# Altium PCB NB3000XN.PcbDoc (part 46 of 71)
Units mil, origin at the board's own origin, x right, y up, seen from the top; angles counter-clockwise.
Board outline 9527.56 x 6929.77 mil, 6 copper layers (Top Layer, GND+SHIELD, MidLayer1, MidLayer2, P2 - 3V3+5V0, Bottom Layer), stack 62.375 mil thick; 832 components, 1027 nets, 4655 pads, 4981 vias.
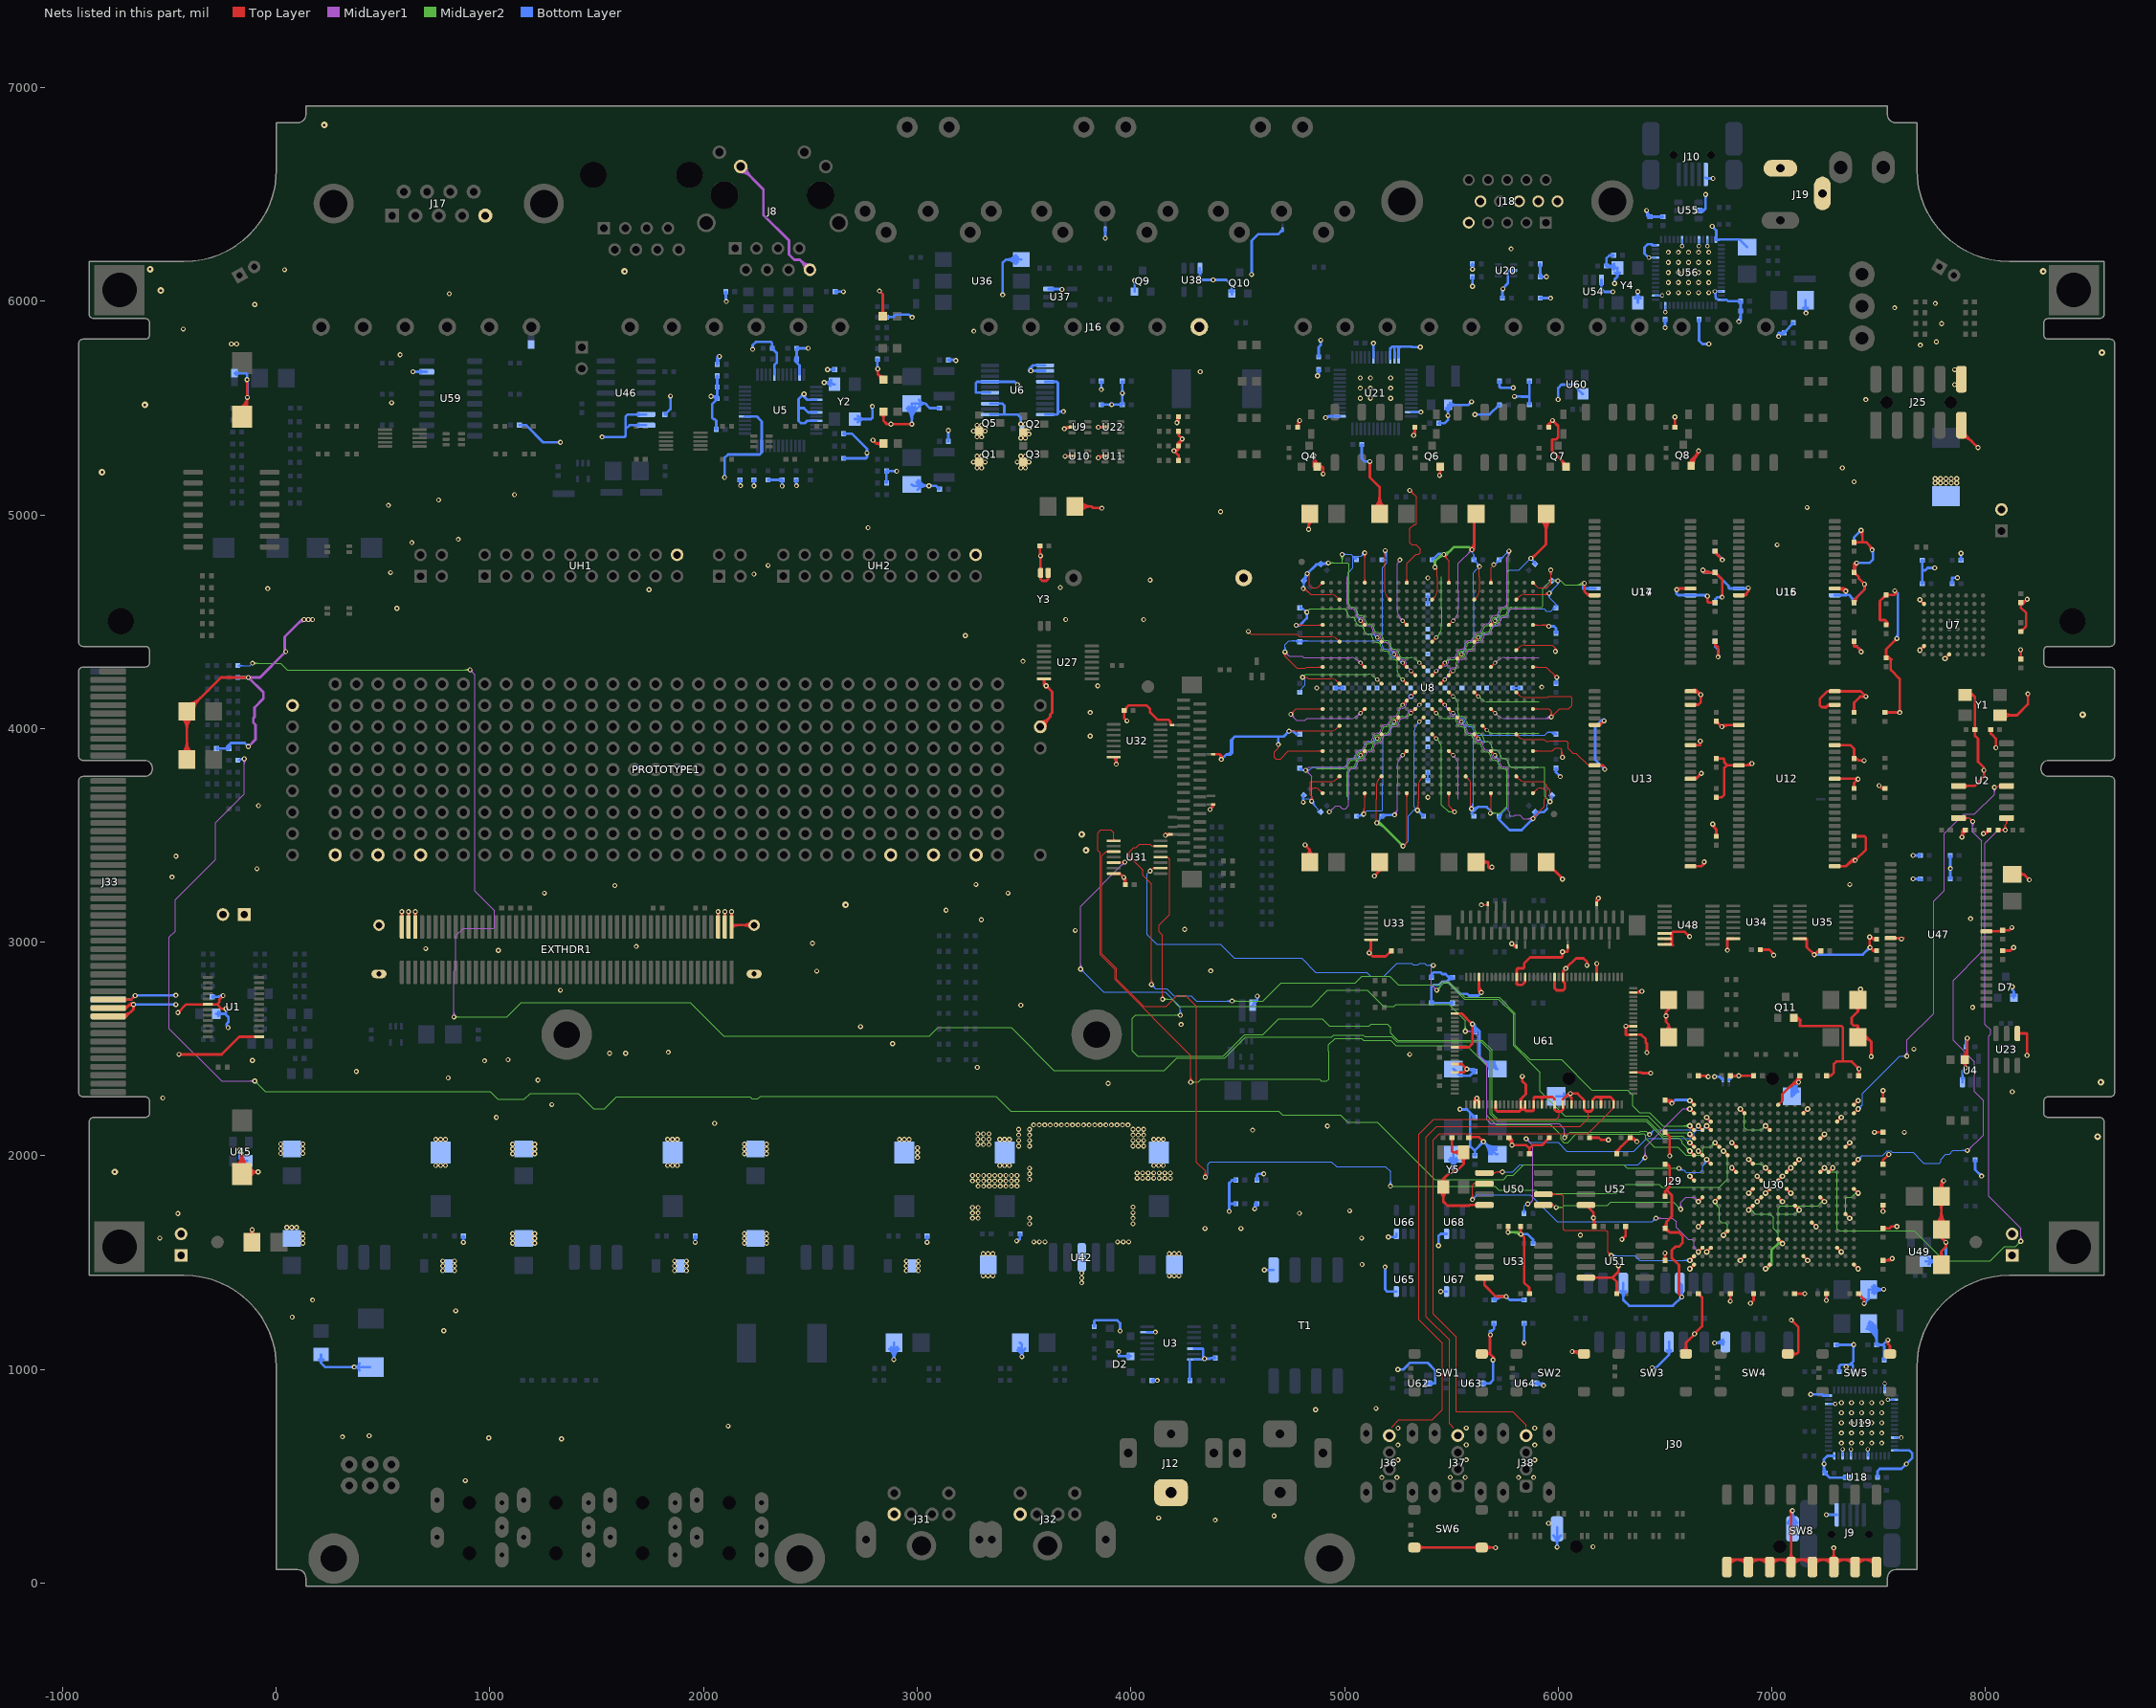
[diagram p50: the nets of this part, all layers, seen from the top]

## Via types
v1: diameter 23, hole 11.81, Top Layer to Bottom Layer, 3672 vias
v2: diameter 26, hole 11.81, Top Layer to Bottom Layer, 461 vias
v3: diameter 19, hole 11.81, Top Layer to Bottom Layer, tented both sides, 396 vias
v4: diameter 23.62, hole 11.81, Top Layer to Bottom Layer, 288 vias
v5: diameter 20, hole 11.81, Top Layer to Bottom Layer, 91 vias
v6: diameter 23, hole 11.81, Top Layer to Bottom Layer, tented both sides, 50 vias
v7: diameter 31, hole 11.81, Top Layer to Bottom Layer, 15 vias
v8: diameter 27.56, hole 11.81, Top Layer to Bottom Layer, tented both sides, 4 vias
v9: diameter 29, hole 11.81, Top Layer to Bottom Layer, 3 vias
v10: diameter 21, hole 11.81, Top Layer to Bottom Layer, 1 vias

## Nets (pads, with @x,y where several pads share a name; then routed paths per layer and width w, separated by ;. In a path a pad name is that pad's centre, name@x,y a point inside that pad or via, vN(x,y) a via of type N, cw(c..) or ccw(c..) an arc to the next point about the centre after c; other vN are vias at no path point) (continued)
GND: (continued)
  Bottom Layer w12: v1@7431.86,1313.87 ccw(c7431.86,1327.15) 7441.25,1317.76 ccw(c7450.64,1308.37) v1@7437.36,1308.37 ; v1(7433.86,4676.04) 7433.86,4651.04 7385.19,4602.37 ; v1@7453.69,2975.04 cw(c7440.41,2975.04) 7449.8,2965.65 cw(c7459.19,2956.26) v1@7459.19,2969.54 ; v1@7465.64,4832.71 cw(c7446.59,4813.66) 7473.52,4813.66 ; C93.2@7469.71,1360.69 cw(c7497.3,1338.74) 7497.3,1374 cw(c7497.3,1409.26) C93.2@7469.71,1387.31 ; C93.2@7479.1,1353.22 cw(c7522.19,1318.94) v1@7522.19,1374 ; C93.2@7479.11,1394.78 ccw(c7522.19,1429.05) v1@7522.19,1374 ; v4(7480,2110) v4@7481.86,2110 ; C90.1@7494.33,495 7494.33,524.33 7505,535 7606.86,535 v1(7629.73,557.88) 7656.86,585 7656.86,608.37 ; 7506.93,1374 ccw(c7506.93,1391.97) v1@7519.64,1379.26 ; v1@7522.52,1374.33 v1@7522.19,1374 ; v1@7522.52,1374.37 v1(7523.52,1375.37) ; v4(7547.7,2006.4) v4@7548.6,2006.4 ; v1(7575.52,4645.04) 7590.19,4630.37 7590.19,4426.37 v1(7585.19,4421.37) ; v1@7581.3,4425.26 ccw(c7559.84,4446.72) 7590.19,4446.72 ; v1@7660,3405 v1(7661.18,3406.18) C238.2@7695.39,3406.18 C238.2@7694.21,3405 ; v1@7661.18,3296.18 C222.2@7695.39,3296.18 ; v1@7665.07,3292.48 cw(c7673.99,3283.56) 7673.99,3296.18 ; v1@7665.07,3300.26 ccw(c7674.92,3310.12) 7674.92,3296.18 ; v1@7665.07,3402.29 cw(c7674.46,3392.9) 7674.46,3406.18 cw(c7674.46,3419.46) v1@7665.07,3410.07 ; C222.2@7691.28,3292.07 ccw(c7681.36,3282.15) 7681.36,3296.18 ccw(c7681.36,3310.21) C222.2@7691.28,3300.29 ; C238.2@7691.28,3402.07 ccw(c7681.36,3392.15) 7681.36,3406.18 ccw(c7681.36,3420.21) C238.2@7691.28,3410.29 ; C222.2@7695.39,3291.71 C222.2@7699.52,3291.71 ; C228.2@7699.55,4682.11 ccw(c7689.63,4692.03) 7703.66,4692.03 ccw(c7717.69,4692.03) C228.2@7707.77,4682.11 ; C227.2@7699.55,4783.89 cw(c7689.63,4773.97) 7703.66,4773.97 cw(c7717.69,4773.97) C227.2@7707.77,4783.89 ; C228.2@7703.66,4678 7703.66,4740 ; C227.2@7703.66,4788 7703.66,4740 ; U49.1@7719.07,1506.69 7806.69,1506.69 7815.19,1515.19 v1(7815.19,1595.04) ; U49.1@7733.62,1492.14 cw(c7768.75,1457.02) 7768.75,1506.69 cw(c7768.75,1556.36) U49.1@7733.62,1521.24 ; v1@7758.3,4748.15 ccw(c7748.91,4738.76) 7748.91,4752.04 ccw(c7748.91,4765.32) v1@7758.3,4755.93 ; v1(7762.19,4752.04) 7728.86,4752.04 7717.86,4741.04 7704.7,4741.04 7703.66,4740 ; C254.2@7831.28,3300.29 ccw(c7821.36,3310.21) 7835.39,3310.21 ccw(c7849.42,3310.21) C254.2@7839.5,3300.29 ; C253.2@7831.28,3402.07 cw(c7821.36,3392.15) 7835.39,3392.15 cw(c7849.42,3392.15) C253.2@7839.5,3402.07 ; v1@7831.64,3341.15 cw(c7822.58,3332.1) 7835.39,3332.1 ; v1@7831.64,3348.93 ccw(c7822.58,3357.99) 7835.39,3357.99 ; C254.2@7835.39,3296.18 7835.39,3344.9 v1(7835.52,3345.04) 7835.39,3345.18 C253.2@7835.39,3406.18 ; 7835.39,3331.43 cw(c7849.14,3331.43) v1@7839.41,3341.15 ; 7835.39,3358.65 ccw(c7849.14,3358.65) v1@7839.41,3348.93 ; C248.2@7839.55,4682.11 ccw(c7829.63,4692.03) 7843.66,4692.03 ccw(c7857.69,4692.03) C248.2@7847.77,4682.11 ; C248.2@7843.66,4678 7843.66,4705.9 7843.8,4706.04 v1(7868.52,4706.04) ; v1@7864.64,4702.15 ccw(c7855.25,4692.76) 7855.25,4706.04 ccw(c7855.25,4719.32) v1@7864.64,4709.93 ; C247.2@7880.89,4792.11 ccw(c7870.97,4802.03) 7885,4802.03 ccw(c7899.03,4802.03) C247.2@7889.11,4792.11 ; v1@7881.3,4816.49 cw(c7872.37,4807.56) 7885,4807.56 ; v1@7881.86,4823.71 v1@7885,4820.56 ; C247.2@7885,4788 7885,4820.37 v1@7885,4820.56 ; 7885,4806.64 cw(c7898.93,4806.64) v1@7889.08,4816.49 ; v1(7885.19,4820.37) v1@7885,4820.56 ; U4.3@7888.49,2362.77 ccw(c7878.57,2372.69) 7892.6,2372.69 ccw(c7906.63,2372.69) U4.3@7896.71,2362.77 ; U4.3@7892.6,2344.88 7892.6,2397.78 v1(7906.86,2412.04) ; C39.1@7905.22,2514.11 ccw(c7895.3,2524.03) 7909.33,2524.03 ccw(c7923.36,2524.03) C39.1@7913.44,2514.11 ; C39.1@7909.33,2510 7909.33,2545.37 7914.66,2550.71 v1(7914.86,2550.71) ; 7909.33,2524.09 cw(c7941.48,2524.09) v1@7918.75,2546.82 ; R163.1@7947.42,1977.41 cw(c7938.34,1968.33) 7951.18,1968.33 cw(c7964.02,1968.33) R163.1@7954.94,1977.41 ; R163.1@7951.18,1981.67 7951.18,1935.68 7981.76,1905.1 v1@7981.86,1905 ; 7972.14,1914.72 ccw(c7981.86,1924.44) v1@7981.86,1910.69 ; 7972.61,1914.25 cw(c7963.55,1905.19) v1@7976.36,1905.19 ; D7.1@8124.12,2749.06 ccw(c8104.11,2769.06) 8132.4,2769.06 ccw(c8160.69,2769.06) D7.1@8140.69,2749.06 ; v1@8126.9,2793.42 8124.74,2795.59 8124.65,2795.59 8125.19,2795.04 v1(8125.19,2791.71) 8125.19,2777.21 8132.4,2770 D7.1@8132.4,2739.79 ; -239.81,2665 -223.5,2648.69 -223.5,2626.09 -233,2616.59 ; 210,1030 228.29,1011.71 v1(365.19,1011.71) v1@365.19,1011.81 ; v1@2435,5141.71 2435.19,5141.71 v1(2435.19,5136.71) 2432.52,5139.37 2434.86,5141.71 v1@2435,5141.71 ; v1@2435,5141.71 2434,5142.71 R41.2@2434,5163.82 2435,5163.82 v1@2435,5141.71 ; 2435.67,5715.97 cw(c2449.7,5715.97) 2439.78,5725.89 ccw(c2449.7,5715.97) 2435.67,5715.97 ; 2435.67,5715.97 ccw(c2421.64,5715.97) 2431.56,5725.89 cw(c2421.64,5715.97) 2435.67,5715.97 ; C47.1@2435.67,5775.04 2438.15,5777.52 C47.1@2440.63,5780 ; C47.1@2435.67,5775.04 C47.1@2435.67,5780 C47.1@2440.63,5780 ; 2445,5455 2445,5500 ; U38.3@4319.14,6137.23 cw(c4308.54,6126.63) 4323.52,6126.63 ccw(c4308.54,6126.63) U38.3@4319.14,6137.23 ; U38.3@4319.14,6137.23 cw(c4309.21,6127.31) 4323.24,6127.31 cw(c4337.27,6127.31) U38.3@4327.35,6137.23 ; U38.3@4327.35,6137.23 ccw(c4336.6,6127.99) 4323.52,6127.99 cw(c4336.6,6127.99) U38.3@4327.35,6137.23 ; 4455,3879.04 4466.19,3879.04 4474.86,3887.71 4474.86,3951.04 ; 4455,3879.04 4468.86,3892.9 4468.86,3945.04 4474.86,3951.04 ; 4474.86,3951.04 4485.86,3962.04 4690.19,3962.04 ; v1@4917.69,4774.2 v1(4924.52,4775.04) 4918.52,4775.04 v1@4917.69,4774.2 ; 5235,5788.21 5263.21,5788.21 ; 5415.06,2858.37 5449.91,2858.37 5457.78,2850.5 5473.06,2850.5 5493.52,2830.04 ; 5480.19,2816.71 5493.52,2830.04 ; 5573.96,2216.71 5587.52,2203.14 ; 5573.96,2216.71 5587.52,2203.14 ; 5587.52,2203.14 C338.2@5610,2180.67 5587.52,2203.14 ; 5587.52,2203.14 5587.52,2041.71 5592.19,2041.71 5608.86,2025.04 ; 5594.19,3603.37 5604.86,3614.04 ; 5594.19,3603.37 5604.86,3614.04 ; C338.2@5600.08,2190.59 cw(c5590.16,2180.67) 5604.19,2180.67 ccw(c5590.16,2180.67) C338.2@5600.08,2190.59 ; C338.2@5600.08,2190.59 ccw(c5610,2200.51) 5610,2186.48 cw(c5610,2200.51) C338.2@5600.08,2190.59 ; 5604.86,3614.04 5606.86,3616.04 ; 5604.86,3614.04 5606.86,3616.04 ; 5606.86,3616.04 5624.19,3633.37 ; v1@5739.52,6058.37 5740.36,6059.21 5764.52,6083.37 5764.52,6135.41 5770.82,6141.71 ; v1@6006.9,3775 v1(6010,3775) v1@6006.86,3778.14 ; v1@6006.86,3775.04 v1@6006.9,3775 ; v1@6006.86,3775.04 v1@6006.86,3778.14 ; 6122.52,4667.43 cw(c6135.8,4667.43) 6126.41,4676.82 ccw(c6135.8,4667.43) 6122.52,4667.43 ; 6122.52,4667.43 ccw(c6109.25,4667.43) 6118.64,4676.82 cw(c6109.25,4667.43) 6122.52,4667.43 ; 6130,4655.75 6115.9,4655.75 6115.9,4674.08 v1(6122.52,4680.71) 6122.52,4663.22 6130,4655.75 ; 6681.86,6425 6690.19,6433.33 ; 7348.52,4625.04 7362.52,4625.04 7385.19,4602.37 ; 5765.93,6136.82 cw(c5780.25,6122.5) 5783.05,6142.55 ccw(c5780.25,6122.5) 5765.93,6136.82 ; C324.2@5895.78,3613.7 ccw(c5908.63,3626.55) 5908.63,3608.37 cw(c5908.63,3626.55) C324.2@5895.78,3613.7
  other v1: 6163,170 5955,280 4395,295 4130,305 4670,315 885,480 5174.79,494.61 5245,494.61 5814.79,494.61 5885,494.61 5494.79,495 5565,495 5250.17,576.71 5890.17,576.71 5570.17,577.1 5250.17,646.92 5570.17,647.31 5890.17,646.92 1335,675 995,680 310,685 435,690 5250.17,725.66 5890.17,725.66 5570.17,726.05 2115,735 5147,818 7348,1013 7383.52,1116.71 4115,1175 784.17,1181.5 75,1245 840,1275 170,1325 5450,1364.88 3770,1406.01 3770,1428.51 3309.02,1438.07 3331.52,1438.07 3354.02,1438.07 4180,1438.07 4202.5,1438.07 4225,1438.07 3770,1451.01 779.17,1462.5 835,1462.5 1864.17,1462.5 1920,1462.5 2949.17,1462.5 3005,1462.5 779.17,1485 835,1485 1864.17,1485 1920,1485 2949.17,1485 3005,1485 5082.52,1491.71 779.17,1507.5 835,1507.5 1864.17,1507.5 1920,1507.5 2949.17,1507.5 3005,1507.5 3309.02,1541.93 3331.52,1541.93 3354.02,1541.93 4180,1541.93 4202.5,1541.93 4225,1541.93 125,1590.98 1106.14,1590.98 1210,1590.98 2191.14,1590.98 2295,1590.98 3546,1597.5 3572,1597.5 3597.99,1597.5 3938.01,1597.5 3964,1597.5 3990,1597.5 125,1613.48 1106.14,1613.48 1210,1613.48 2191.14,1613.48 2295,1613.48 -545,1615 5080,1615 6104,1629 125,1635.98 1106.14,1635.98 1210,1635.98 2191.14,1635.98 2295,1635.98 4347,1660 4515,1660 50.08,1664.92 72.58,1664.92 95.08,1664.92 3526,1682.01 4010,1682.01 3259.02,1708 3285.02,1708 3526,1708.01 4010,1708.01 -460,1730 4789,1731 3259.02,1733 3285.02,1733 4010,1734 5024,1743 3259.02,1758 3285.02,1758 4010,1760 3285.02,1858 3311.01,1858 3337.01,1858 3363,1858 3389,1858 3415,1858 3440.99,1858 3466.99,1858 3259.02,1883 3285.02,1883 3311.01,1883 3337.01,1883 3363,1883 3389,1883 3415,1883 3440.99,1883 3466.99,1883 3526,1889.98 4029.02,1895 4055.02,1895 4081.01,1895 4107.01,1895 4133,1895 4159,1895 4185,1895 7981.86,1905.19 3259.02,1908 3285.02,1908 3311.01,1908 3337.01,1908 3363,1908 3389,1908 3415,1908 3440.99,1908 3466.99,1908 3526,1915.98 4029.02,1920 4055.02,1920 4081.01,1920 4107.01,1920 4133,1920 4159,1920 4185,1920 3526.01,1941.97 747.01,1954.88 769.51,1954.88 792.01,1954.88 1832.01,1954.88 1854.51,1954.88 1877.01,1954.88 3386.46,1954.88 3408.96,1954.88 3431.46,1954.88 4107.01,1954.88 4129.51,1954.88 4152.01,1954.88 3001.3,1992.64 1106.14,2010 1210,2010 2191.14,2010 2295,2010 21.14,2010.98 125,2010.98 3001.3,2015.14 1106.14,2032.5 1210,2032.5 2191.14,2032.5 2295,2032.5 21.14,2033.48 125,2033.48 3001.3,2037.64 3474.99,2045.96 3526.01,2045.96 4009.99,2045.96 4034.99,2045.96 4059.99,2045.96 3284.02,2053 3310.02,2053 3336.01,2053 1106.14,2055 1210,2055 2191.14,2055 2295,2055 21.14,2055.98 125,2055.98 3474.99,2071.95 3526.01,2071.95 4009.99,2071.95 4034.99,2071.95 4059.99,2071.95 747.01,2076.93 769.51,2076.93 792.01,2076.93 1832.01,2076.93 1854.51,2076.93 1877.01,2076.93 2917.01,2076.93 2939.51,2076.93 2962.01,2076.93 3386.46,2076.93 3408.96,2076.93 3431.46,2076.93 4107.01,2076.93 4129.51,2076.93 4152.01,2076.93 3284.02,2078 3310.02,2078 3336.01,2078 3474.99,2097.95 3526.01,2097.95 4009.99,2097.95 4034.99,2097.95 4059.99,2097.95 3284.02,2103 3310.02,2103 3336.01,2103 7620,2110 4570,2120 3474.99,2123.94 3526.01,2123.94 4009.99,2123.94 4034.99,2123.94 4059.99,2123.94 4920,2140 3545,2145 3571,2145 3596.99,2145 3622.99,2145 3648.98,2145 3674.98,2145 3700.98,2145 3726.97,2145.01 3752.97,2145.01 3778.96,2145.01 3804.96,2145.01 3830.96,2145.01 3856.95,2145.01 3882.95,2145.01 3908.94,2145.01 3934.94,2145.01 3960.94,2145.01 3986.93,2145.01 2052,2152 1030,2180 1290,2240 -531,2271 8125,2300 3893.94,2338.94 1225,2355 805,2365 6702.52,2370.71 375,2395 3281,2414 975,2445 1085,2450 5305,2475 1560,2480 1635,2480 1835,2485 7665,2500 2885,2525 2735,2605 4235,2615 7940,2695 1330,2775 7415,2780 2530,2865 4374,2866 7009,2939 700,2970 1685,2980 5782.86,2993.04 2510,2995 3740,3055 4252,3060 3300,3105 7930,3110 619.35,3143.04 650.85,3143.04 2068.17,3143.04 2099.67,3143.04 2131.17,3143.04 3135,3150 1255,3230 3425,3230 1585,3265 3275,3270 7365,3270 7661.18,3296.37 -90,3344 -83,3639 5390,3678 3810,3965 3810,4075 4870,4190 5923,4194 3845,4200 3495,4315 45,4360 3225,4435 3695,4510 4060,4510 565,4563 1745,4650 -40,4655 3670,4660 4090,4695 5390,4705 2236,4723 535,4730 2302,4764 7025,4860 635,4870 852,4886 2770,4940 4420,5015 7165,5035 525,5045 760,5070 1115,5095 7385,5155 3280,5220 3301.57,5220 3485,5220 3506.57,5220 7330,5220 3263.19,5247.6 3318.39,5247.6 3468.19,5247.6 3523.39,5247.6 3280,5275.2 3301.57,5275.2 3485,5275.2 3506.57,5275.2 3485,5360 3506.57,5360 3280,5365 3301.57,5365 3523.39,5378.6 3263.19,5392.6 3318.39,5392.6 3689,5403 3523.39,5406.6 3280,5420.2 3301.57,5420.2 2877,5425 3506.57,5425.2 5484.37,5465 3685,5483.57 3910,5516.37 540,5525 7440,5540 3861.86,5586.9 7855,5610 4325,5670 7855,5680 580,5750 2490,5780 7695,5795 5135.19,5804.04 7770,5810 3265,5860 -435,5870 7795,5895 7160,5945 7575,5970 -100,5985 7765,5990 810,6035 6372.5,6045.19 4385,6100.04 39.01,6147.63 5780,6245 3880,6295 6690,6500
  other v4: 4865,812 -112,2446 3485,2705 1040,2962 -488,3305 -469,3403 7764.51,5149.9 7789.61,5149.9 7814.7,5149.9 7839.8,5149.9 7864.8,5150 7764.51,5169.9 7789.61,5169.9 7814.7,5169.9 7839.8,5169.9 7864.8,5170 5074.13,5546.38 5121.38,5546.38 5215.87,5546.38 5074.13,5593.62 5121.38,5593.62 5215.87,5593.62 5074.13,5640.87 5121.38,5640.87 5215.87,5640.87 -210,5800 -185,5800
  other v5: 7528.27,935.66
  other v6: 7325.51,655.51 7372.76,655.51 7420,655.51 7467.24,655.51 7514.49,655.51 7325.51,702.76 7372.76,702.76 7420,702.76 7467.24,702.76 7514.49,702.76 7325.51,750 7372.76,750 7420,750 7467.24,750 7514.49,750 7325.51,797.24 7372.76,797.24 7420,797.24 7467.24,797.24 7514.49,797.24 7325.51,844.49 7372.76,844.49 7420,844.49 7467.24,844.49 7514.49,844.49 6515.51,6040.51 6562.76,6040.51 6610,6040.51 6657.24,6040.51 6704.49,6040.51 6515.51,6087.76 6562.76,6087.76 6610,6087.76 6657.24,6087.76 6704.49,6087.76 6515.51,6135 6562.76,6135 6610,6135 6657.24,6135 6704.49,6135 6515.51,6182.24 6562.76,6182.24 6610,6182.24 6657.24,6182.24 6704.49,6182.24 6515.51,6229.49 6562.76,6229.49 6610,6229.49 6657.24,6229.49 6704.49,6229.49
  other v7: -755.79,1925 8525,2090 8540,2345 2665,3175 3790,3430 3770,3505 8455,4065 -815,5200 -615,5515 8545,5760 -540,6050 1630,6140 8270,6140 -590,6150 225,6825
GOLD_FLASH.DIN: U30.W12 U50.5 | length 1141.5
  Top Layer w4: U50.5@5930.59,1770 5976.9,1770 ; U50.5@5971.2,1766 cw(c5976.9,1763.94) 5976.9,1770 ; U50.5@5971.2,1774 ccw(c5976.9,1776.06) 5976.9,1770 ; v1(5990.19,1758.37) 5988.52,1758.37 5976.9,1770
  Top Layer w8: v2(6655.67,1786.26) U30.W12@6675.35,1805.94 ; v2@6655.67,1795.26 ccw(c6655.67,1816.99) 6671.03,1801.62 ccw(c6686.4,1786.26) v2@6664.67,1786.26 ; U30.W12@6669.51,1805.94 cw(c6655.41,1805.94) 6665.38,1795.97 cw(c6675.35,1786) U30.W12@6675.35,1800.1
  MidLayer1 w4: v1@6566.81,1756.76 ccw(c6550.59,1772.98) 6573.52,1772.98 ccw(c6596.46,1772.98) v1@6580.24,1756.76 ; v1@6569.64,1753.93 ccw(c6560.25,1763.32) 6573.52,1763.32 ccw(c6586.8,1763.32) v1@6577.41,1753.93 ; v1(6573.52,1750.04) 6573.52,1781.04 6598.52,1806.04 6635.89,1806.04 v2(6655.67,1786.26) ; v2@6644.67,1786.26 ccw(c6618.11,1786.26) 6636.89,1805.04 ccw(c6655.67,1823.82) v2@6655.67,1797.26 ; v2@6648.67,1786.26 ccw(c6631.77,1786.26) 6643.72,1798.21 ccw(c6655.67,1810.16) v2@6655.67,1793.26
  MidLayer2 w4: v1(5990.19,1758.37) 6019.21,1758.37 6029.54,1768.71 6230.88,1768.71 6245.54,1783.37 6540.19,1783.37 v1(6573.52,1750.04) ; v1@5994.08,1754.49 cw(c6003.47,1745.1) 6003.47,1758.37 cw(c6003.47,1771.65) v1@5994.08,1762.26 ; v1@5996.91,1751.66 cw(c6013.13,1735.44) 6013.13,1758.37 cw(c6013.13,1781.31) v1@5996.91,1765.09 ; v1@6564.02,1750.04 ccw(c6541.09,1750.04) 6557.31,1766.26 ccw(c6573.52,1782.48) v1@6573.52,1759.54 ; v1@6568.02,1750.04 ccw(c6554.75,1750.04) 6564.14,1759.43 ccw(c6573.52,1768.82) v1@6573.52,1755.54
GOLD_FLASH.DOUT: U30.W18 U50.2 | length 1681.4
  Top Layer w4: v1@5591.81,1802.43 ccw(c5575.59,1818.64) 5598.52,1818.64 ccw(c5621.46,1818.64) v1@5605.24,1802.43 ; v1@5594.64,1799.6 ccw(c5585.25,1808.99) 5598.52,1808.99 ccw(c5611.8,1808.99) v1@5602.41,1799.6 ; v1(5598.52,1795.71) 5598.52,1862 5606.52,1870 ; U50.2@5614.91,1864.79 ccw(c5606.52,1860.65) 5606.52,1870 ; U50.2@5614.91,1875.21 cw(c5606.53,1879.35) 5606.53,1870 ; U50.2@5655,1870 5606.52,1870
  Top Layer w8: v2(6655.67,1550.04) U30.W18@6675.35,1569.72 ; v2@6655.67,1559.04 ccw(c6655.67,1580.77) 6671.03,1565.4 ccw(c6686.4,1550.04) v2@6664.67,1550.04 ; U30.W18@6669.51,1569.72 cw(c6655.41,1569.72) 6665.38,1559.75 cw(c6675.35,1549.78) U30.W18@6675.35,1563.88
  MidLayer1 w4: v1(6457.86,1708.37) 6535.52,1708.37 6552.19,1691.71 6552.19,1665.71 6608.19,1609.71 6625.86,1609.71 6635.52,1600.04 6635.52,1574.18 6640.19,1569.52 6640.19,1565.52 v2(6655.67,1550.04) ; v1@6461.75,1704.49 cw(c6471.14,1695.1) 6471.14,1708.37 cw(c6471.14,1721.65) v1@6461.75,1712.26 ; v1@6464.57,1701.66 cw(c6480.79,1685.44) 6480.79,1708.37 cw(c6480.79,1731.31) v1@6464.57,1715.09
  Bottom Layer w4: v1(5598.52,1795.71) 5619.52,1816.71 5870.92,1816.71 5995.92,1691.71 6441.19,1691.71 v1(6457.86,1708.37) ; v1@5598.52,1801.21 ccw(c5598.52,1814.49) 5607.91,1805.1 ccw(c5617.3,1795.71) v1@5604.02,1795.71 ; v1@5598.52,1805.21 ccw(c5598.52,1828.14) 5614.74,1811.93 ccw(c5630.96,1795.71) v1@5608.02,1795.71 ; v1@6448.36,1708.37 cw(c6425.42,1708.37) 6441.64,1692.16 cw(c6457.86,1675.94) v1@6457.86,1698.87 ; v1@6452.36,1708.37 cw(c6439.08,1708.37) 6448.47,1698.99 cw(c6457.86,1689.6) v1@6457.86,1702.87
GOLD_FLASH.FLASH_CS_N: U30.Y2 U50.1 | length 1461.2
  Top Layer w4: U50.1@5655,1920 5704.52,1920 ; U50.1@5694.83,1914.29 cw(c5704.52,1908.92) 5704.52,1920 ; U50.1@5694.83,1925.71 ccw(c5704.52,1931.08) 5704.52,1920 ; v1@5732.47,1918.32 ccw(c5716.26,1902.11) 5716.26,1925.04 ccw(c5716.26,1947.98) v1@5732.47,1931.76 ; v1@5735.3,1921.15 ccw(c5725.91,1911.76) 5725.91,1925.04 ccw(c5725.91,1938.32) v1@5735.3,1928.93 ; v1(5739.19,1925.04) 5709.57,1925.04 5704.52,1920
  Top Layer w8: v2@6616.3,2210.33 cw(c6616.3,2188.6) 6631.66,2203.97 cw(c6647.03,2219.33) v2@6625.3,2219.33 ; v2(6616.3,2219.33) U30.Y2@6635.98,2199.65 ; U30.Y2@6630.14,2199.65 ccw(c6616.04,2199.65) 6626.01,2209.62 ccw(c6635.98,2219.59) U30.Y2@6635.98,2205.49
  MidLayer1 w4: v1@6400.14,1998.43 ccw(c6383.92,2014.64) 6406.86,2014.64 ccw(c6429.79,2014.64) v1@6413.57,1998.43 ; v1@6402.97,1995.6 ccw(c6393.58,2004.99) 6406.86,2004.99 ccw(c6420.14,2004.99) v1@6410.75,1995.6 ; v1(6406.86,1991.71) 6406.86,2041.71 6584.48,2219.33 v2(6616.3,2219.33) ; v2@6608.52,2211.55 ccw(c6589.74,2192.77) 6589.74,2219.33 ccw(c6589.74,2245.89) v2@6608.52,2227.11 ; v2@6611.35,2214.38 ccw(c6599.4,2202.43) 6599.4,2219.33 ccw(c6599.4,2236.23) v2@6611.35,2224.28
  Bottom Layer w4: v1(5739.19,1925.04) 5787.52,1925.04 5820.52,1958.04 6373.19,1958.04 v1(6406.86,1991.71) ; v1@6397.36,1991.71 cw(c6374.42,1991.71) 6390.64,1975.49 cw(c6406.86,1959.27) v1@6406.86,1982.21 ; v1@6401.36,1991.71 cw(c6388.08,1991.71) 6397.47,1982.32 cw(c6406.86,1972.93) v1@6406.86,1986.21
GOLD_FLASH.SCLK: U30.Y19 U50.6 | length 1299.2
  Top Layer w4: U50.6@5930.59,1820 6015,1820 6023.52,1811.48 6023.52,1656.48 6028.96,1651.04 6223.52,1651.04 6231.86,1642.71 6231.86,1550.04 v1(6248.52,1533.37) ; U50.6@5965.62,1814.5 cw(c5978.9,1801.22) 5978.9,1820 cw(c5978.9,1838.78) U50.6@5965.62,1825.5 ; U50.6@5968.45,1811.67 cw(c5988.56,1791.56) 5988.56,1820 cw(c5988.56,1848.44) U50.6@5968.45,1828.33 ; v1@6239.02,1533.37 ccw(c6216.09,1533.37) 6232.31,1549.59 ccw(c6248.52,1565.81) v1@6248.52,1542.87 ; v1@6243.02,1533.37 ccw(c6229.75,1533.37) 6239.13,1542.76 ccw(c6248.52,1552.15) v1@6248.52,1538.87
  Top Layer w8: v2(6616.3,1510.67) U30.Y19@6635.98,1530.35 ; v2@6616.3,1519.67 ccw(c6616.3,1541.4) 6631.66,1526.03 ccw(c6647.03,1510.67) v2@6625.3,1510.67 ; U30.Y19@6630.14,1530.35 cw(c6616.04,1530.35) 6626.01,1520.38 cw(c6635.98,1510.41) U30.Y19@6635.98,1524.51
  Bottom Layer w4: v1(6248.52,1533.37) 6357.29,1533.37 6380,1510.67 v2(6616.3,1510.67) ; v1@6252.41,1529.49 cw(c6261.8,1520.1) 6261.8,1533.37 cw(c6261.8,1546.65) v1@6252.41,1537.26 ; v1@6255.24,1526.66 cw(c6271.46,1510.44) 6271.46,1533.37 cw(c6271.46,1556.31) v1@6255.24,1540.09 ; v2@6608.52,1502.89 ccw(c6589.74,1484.11) 6589.74,1510.67 ccw(c6589.74,1537.23) v2@6608.52,1518.45 ; v2@6611.35,1505.72 ccw(c6599.4,1493.77) 6599.4,1510.67 ccw(c6599.4,1527.57) v2@6611.35,1515.62
HOST_AUDIO.L: R1.1 U30.V8 | length 9648.9
  Top Layer w8: v2@6695.04,1974.11 cw(c6695.04,1952.38) 6710.4,1967.75 cw(c6725.77,1983.11) v2@6704.04,1983.11 ; v2(6695.04,1983.11) U30.V8@6714.72,1963.43 ; U30.V8@6708.88,1963.43 ccw(c6694.78,1963.43) 6704.75,1973.4 ccw(c6714.72,1983.37) U30.V8@6714.72,1969.27
  MidLayer1 w4: v1@-156.19,3851.66 cw(c-172.41,3835.44) -149.48,3835.44 cw(c-126.54,3835.44) v1@-142.76,3851.66 ; v1@-153.36,3854.49 cw(c-162.75,3845.1) -149.48,3845.1 cw(c-136.2,3845.1) v1@-145.59,3854.49 ; v1(-149.48,3858.37) -149.48,3694.33 -283.81,3560 -283.81,3387.7 -472.5,3199.01 -472.5,3052.25 -500.19,3024.56 -500.19,2595.44 -254.25,2349.5 v1@-101.02,2349.5 ; -124.72,2349.5 ccw(c-124.72,2374.28) v1@-107.19,2356.76 ; -122.11,2349.5 cw(c-122.11,2328.41) v1@-107.19,2343.32 ; -115.06,2349.5 ccw(c-115.06,2364.62) v1@-104.36,2353.93 ; -112.45,2349.5 cw(c-112.45,2338.07) v1@-104.36,2346.15
  MidLayer2 w4: v1@-100.48,2340.54 cw(c-100.48,2317.61) -84.26,2333.82 cw(c-68.04,2350.04) v1@-90.98,2350.04 ; v1@-100.48,2344.54 cw(c-100.48,2331.26) -91.09,2340.65 cw(c-81.7,2350.04) v1@-94.98,2350.04 ; v1(-100.48,2350.04) -50.44,2300 1001.31,2300 1036.31,2265 1161.31,2265 1188.69,2292.37 1412.63,2292.37 1485,2220 1535.92,2220 1549.21,2233.29 1591.92,2276 2216.62,2276 2226.12,2266.5 2253.88,2266.5 2265.88,2278.5 3368.88,2278.5 3437.38,2210 4691.71,2210 4710,2191.71 4981.86,2191.71 5015.19,2158.37 5153.88,2158.37 5422.38,1889.87 5743.96,1889.87 5762.96,1908.87 5789.36,1908.87 5838.19,1957.71 6305.86,1957.71 6321.86,1941.71 v1(6565.19,1941.71) ; v1@6558.47,1934.99 ccw(c6542.26,1918.77) 6542.26,1941.71 ccw(c6542.26,1964.64) v1@6558.47,1948.43 ; v1@6561.3,1937.82 ccw(c6551.91,1928.43) 6551.91,1941.71 ccw(c6551.91,1954.99) v1@6561.3,1945.6
  Bottom Layer w4: R1.1@-178.82,3851.36 R1.1@-171.81,3858.37 ; R1.1@-177.72,3851.13 cw(c-164.3,3842.32) -164.3,3858.37 ; R1.1@-174.37,3848.94 cw(c-156.89,3837.46) v1@-156.89,3858.37 ; R1.1@-171.03,3846.74 cw(c-149.48,3832.6) v1(-149.48,3858.37) R1.1@-171.81,3858.37 ; v1@-156.32,3851.79 ccw(c-171.81,3836.88) R1.1@-171.81,3858.37 ; v1@-156.32,3864.96 cw(c-171.81,3879.87) R1.1@-171.81,3858.37 ; v1@-153.44,3854.56 ccw(c-162.4,3845.93) -162.4,3858.37 ccw(c-162.4,3870.82) v1@-153.44,3862.19 ; v1(6565.19,1941.71) 6573.52,1933.37 6588.86,1933.37 ; v1@6566.63,1942.12 ccw(c6578.24,1945.45) 6578.24,1933.37 ; v1@6570.48,1943.22 ccw(c6583.55,1946.97) 6583.55,1933.37 ; v1@6574.32,1944.33 ccw(c6588.86,1948.49) 6588.86,1933.37 ; 6681.3,1957.15 ccw(c6667.95,1970.5) v2@6685.07,1978.47 ; 6685.34,1961.19 ccw(c6673.47,1973.07) v2@6688.69,1980.16 ; 6689.39,1965.24 ccw(c6678.98,1975.64) v2@6692.32,1981.84 ; 6693.43,1969.28 ccw(c6684.5,1978.2) v2@6695.95,1983.53 ; v2(6695.04,1983.11) 6695.04,1970.89 6675.19,1951.04 6675.19,1933.37 6665.52,1923.71 6598.52,1923.71 6588.86,1933.37
HOST_AUDIO.R: R14.1 U30.Y7 | length 9885
  Top Layer w8: v2@6616.3,2013.48 cw(c6616.3,1991.75) 6631.66,2007.12 cw(c6647.03,2022.48) v2@6625.3,2022.48 ; v2(6616.3,2022.48) U30.Y7@6635.98,2002.8 ; U30.Y7@6630.14,2002.8 ccw(c6616.04,2002.8) 6626.01,2012.77 ccw(c6635.98,2022.74) U30.Y7@6635.98,2008.64
  MidLayer1 w4: v1@825.14,2656.76 ccw(c808.92,2672.98) 831.86,2672.98 ccw(c854.79,2672.98) v1@838.57,2656.76 ; v1@827.97,2653.93 ccw(c818.58,2663.32) 831.86,2663.32 ccw(c845.14,2663.32) v1@835.75,2653.93 ; v1(831.86,2650.04) 831.86,2863.37 840.19,2871.71 840.19,2995 ; 840,2995 840,3030 875.71,3065.71 1018.08,3065.71 1022,3069.63 1022,3148 930,3240 930,4251.9 v1(906.86,4275.04) ; v1@906.86,4265.54 cw(c906.86,4242.61) 923.07,4258.82 cw(c939.29,4275.04) v1@916.36,4275.04 ; v1@906.86,4269.54 cw(c906.86,4256.26) 916.25,4265.65 cw(c925.64,4275.04) v1@912.36,4275.04
  MidLayer2 w4: v1(-110.81,4306.04) 20,4306.04 51,4275.04 v1(906.86,4275.04) ; v1@-106.92,4302.15 cw(c-97.53,4292.76) -97.53,4306.04 cw(c-97.53,4319.32) v1@-106.92,4309.93 ; v1@-104.09,4299.32 cw(c-87.87,4283.11) -87.87,4306.04 cw(c-87.87,4328.98) v1@-104.09,4312.76 ; v1(831.86,2650.04) 1080,2650.04 1146.67,2716.71 1936.98,2716.71 2093.69,2560 3056.27,2560 3096.98,2600.71 3439.29,2600.71 3640.63,2399.37 4156,2399.37 4215,2458.37 4438.19,2458.37 4537.19,2557.37 4940,2557.37 4948.62,2566 5086.86,2566 5095.36,2557.5 5221.5,2557.5 5245.63,2533.37 5640.19,2533.37 5682.86,2490.71 5682.86,2194.77 5715.25,2162.37 6411.19,2162.37 6490.19,2083.37 6565.19,2083.37 6580,2068.56 6580,2058.78 v2@6615.19,2023.59 ; v1@835.75,2646.15 cw(c845.14,2636.76) 845.14,2650.04 cw(c845.14,2663.32) v1@835.75,2653.93 ; v1@838.57,2643.32 cw(c854.79,2627.11) 854.79,2650.04 cw(c854.79,2672.98) v1@838.57,2656.76 ; v1@900.14,4268.32 ccw(c883.92,4252.11) 883.92,4275.04 ccw(c883.92,4297.98) v1@900.14,4281.76 ; v1@902.97,4271.15 ccw(c893.58,4261.76) 893.58,4275.04 ccw(c893.58,4288.32) v1@902.97,4278.93 ; v2@6605.3,2022.48 ccw(c6578.74,2022.48) 6597.52,2041.26 ccw(c6616.3,2060.04) v2@6616.3,2033.48 ; v2@6609.3,2022.48 ccw(c6592.4,2022.48) 6604.35,2034.43 ccw(c6616.3,2046.38) v2@6616.3,2029.48 ; v2@6615.19,2022.48 v2@6615.19,2023.59 ; v2(6616.3,2022.48) v2@6615.19,2023.59
  Bottom Layer w4: R14.1@-176.48,4295.71 -176.48,4295.49 -178.82,4295.49 R14.1@-178.82,4295 -121.85,4295 v1(-110.81,4306.04) ; R14.1@-175.06,4291.24 cw(c-165.98,4282.16) -165.98,4295 cw(c-165.98,4307.84) R14.1@-175.06,4298.76 ; R14.1@-172.23,4288.41 cw(c-156.32,4272.5) -156.32,4295 cw(c-156.32,4317.5) R14.1@-172.23,4301.59
HOST_CLK.CS_N: R30.1 U2.9 U30.E9 | length 3928.6
  Top Layer w4: R30.1@8059.51,3525 8076.48,3525 ; R30.1@8067.38,3520 cw(c8076.48,3514.21) 8076.48,3525 ; R30.1@8067.38,3530 ccw(c8076.48,3535.79) 8076.48,3525 ; v1@8084.18,3520.49 ccw(c8076.52,3516.32) 8076.52,3525.04 ; v1@8084.18,3529.59 cw(c8076.52,3533.76) 8076.52,3525.04 ; v1@8085.81,3531.76 ccw(c8069.59,3547.98) 8092.52,3547.98 ccw(c8115.46,3547.98) v1@8099.24,3531.76 ; v1@8088.64,3528.93 ccw(c8079.25,3538.32) 8092.52,3538.32 ccw(c8105.8,3538.32) v1@8096.41,3528.93 ; U2.9@8090.73,3572.56 cw(c8075.03,3555) 8098.58,3555 ; U2.9@8093.4,3575.54 cw(c8083.03,3563.94) 8098.58,3563.94 cw(c8114.14,3563.95) U2.9@8103.77,3575.54 ; U2.9@8098.58,3581.34 8098.58,3555 ; U2.9@8106.44,3572.56 ccw(c8122.14,3555) 8098.58,3555 ; 8076.48,3525 8076.52,3525.04 ; 8076.52,3525.04 v1(8092.52,3525.04) 8092.52,3548.94 8098.58,3555
  Top Layer w8: U30.E9@7226.54,1924.06 v2(7246.22,1943.74) ; U30.E9@7226.54,1929.9 ccw(c7226.54,1944) 7236.51,1934.03 ccw(c7246.48,1924.06) U30.E9@7232.38,1924.06 ; v2@7237.22,1943.74 cw(c7215.49,1943.74) 7230.86,1928.38 cw(c7246.22,1913.01) v2@7246.22,1934.74
  MidLayer1 w4: v1@8085.81,3518.32 ccw(c8069.59,3502.11) 8069.59,3525.04 ccw(c8069.59,3547.98) v1@8085.81,3531.76 ; v1@8088.64,3521.15 ccw(c8079.25,3511.76) 8079.25,3525.04 ccw(c8079.25,3538.32) v1@8088.64,3528.93 ; v1(8092.52,3525.04) 8059.84,3525.04 7997.86,3463.06 7997.86,2615.67 8023.52,2590 8023.52,2569.71 8015.19,2561.37 8015.48,2561.09 8015.48,1811.35 8165.19,1661.64 v1(8165.19,1600.04) ; v1@8158.47,1606.76 ccw(c8142.26,1622.98) 8165.19,1622.98 ccw(c8188.13,1622.98) v1@8171.91,1606.76 ; v1@8161.3,1603.93 ccw(c8151.91,1613.32) 8165.19,1613.32 ccw(c8178.47,1613.32) v1@8169.08,1603.93
  MidLayer2 w4: v2@7246.22,1932.74 cw(c7246.22,1906.18) 7265,1924.96 ; v2@7246.22,1936.74 cw(c7246.22,1919.84) 7258.17,1931.79 cw(c7270.12,1943.74) v2@7253.22,1943.74 ; v2(7246.22,1943.74) 7265.92,1924.04 7303.52,1924.04 7305.19,1922.37 7305.19,1889.04 7305.96,1888.27 7305.96,1659.04 7316.63,1648.37 7666.86,1648.37 7806.86,1508.37 8021.86,1508.37 8088.52,1575.04 8140.19,1575.04 v1(8165.19,1600.04) ; v2@7257.22,1943.74 ccw(c7283.78,1943.74) 7265,1924.96 ; v1@8155.69,1600.04 cw(c8132.76,1600.04) 8148.97,1583.82 cw(c8165.19,1567.61) v1@8165.19,1590.54 ; v1@8159.69,1600.04 cw(c8146.41,1600.04) 8155.8,1590.65 cw(c8165.19,1581.26) v1@8165.19,1594.54
HOST_CLK.DIN: U2.12 U30.A2 | length 2217.6
  Top Layer w4: v1(8041.86,3725.04) 8053.7,3725.04 8060,3731.34 ; U2.12@8065.88,3727.24 ccw(c8060,3725.06) 8060,3731.34 ; U2.12@8065.88,3735.43 cw(c8060,3737.61) 8060,3731.34 ; U2.12@8098.58,3731.34 8060,3731.34
  Top Layer w8: U30.A2@7384.02,2199.65 v2(7403.7,2219.33) ; U30.A2@7384.02,2205.49 ccw(c7384.02,2219.59) 7393.99,2209.62 ccw(c7403.96,2199.65) U30.A2@7389.86,2199.65 ; v2@7394.7,2219.33 cw(c7372.97,2219.33) 7388.34,2203.97 cw(c7403.7,2188.6) v2@7403.7,2210.33
  MidLayer1 w4: v1@7625.14,2473.43 ccw(c7608.92,2489.64) 7631.86,2489.64 ccw(c7654.79,2489.64) v1@7638.57,2473.43 ; v1@7627.97,2470.6 ccw(c7618.58,2479.99) 7631.86,2479.99 ccw(c7645.14,2479.99) v1@7635.75,2470.6 ; v1(7631.86,2466.71) 7631.86,2542.04 7756.86,2667.04 7756.86,3191.71 7806.86,3241.71 7806.86,3508.37 7897.86,3599.37 7949.12,3599.37 8041.86,3692.11 v1(8041.86,3725.04) ; v1@8035.14,3718.32 cw(c8018.92,3702.11) 8041.86,3702.11 cw(c8064.79,3702.11) v1@8048.57,3718.32 ; v1@8037.97,3721.15 cw(c8028.58,3711.76) 8041.86,3711.76 cw(c8055.14,3711.76) v1@8045.75,3721.15
  Bottom Layer w4: v2(7403.7,2219.33) 7423.52,2239.15 7423.52,2292.37 7597.86,2466.71 v1(7631.86,2466.71) ; v2@7403.7,2226.33 ccw(c7403.7,2243.23) 7415.65,2231.28 ccw(c7427.6,2219.33) v2@7410.7,2219.33 ; v2@7403.7,2230.33 ccw(c7403.7,2256.89) 7422.48,2238.11 ccw(c7441.26,2219.33) v2@7414.7,2219.33 ; v1@7625.14,2459.99 ccw(c7608.92,2443.77) 7608.92,2466.71 ccw(c7608.92,2489.64) v1@7625.14,2473.43 ; v1@7627.97,2462.82 ccw(c7618.58,2453.43) 7618.58,2466.71 ccw(c7618.58,2479.99) v1@7627.97,2470.6
HOST_CLK.SCLK: U2.8 U30.A8 | length 2810.3
  Top Layer w4: U2.8@7874.17,3581.34 7924.23,3581.34 ; U2.8@7901.33,3575.84 cw(c7914.58,3562.62) 7914.58,3581.34 cw(c7914.58,3600.06) U2.8@7901.33,3586.83 ; U2.8@7904.16,3573.02 cw(c7924.22,3553) 7924.22,3581.34 ; U2.8@7904.16,3589.66 ccw(c7924.22,3609.68) 7924.22,3581.34 ; v1@7930.69,3565.48 ccw(c7908.62,3565.73) 7924.23,3581.34 ; v1@7934.69,3565.44 ccw(c7921.91,3565.58) 7930.95,3574.62 ccw(c7939.98,3583.65) v1@7940.13,3570.87 ; v1@7940.08,3574.87 cw(c7939.84,3596.95) 7924.23,3581.34 ; v1(7940.19,3565.37) 7924.23,3581.34
  Top Layer w8: U30.A8@7384.02,1963.43 v2(7403.7,1983.11) ; U30.A8@7384.02,1969.27 ccw(c7384.02,1983.37) 7393.99,1973.4 ccw(c7403.96,1963.43) U30.A8@7389.86,1963.43 ; v2@7394.7,1983.11 cw(c7372.97,1983.11) 7388.34,1967.75 cw(c7403.7,1952.38) v2@7403.7,1974.11
  MidLayer1 w4: v1(7915,2025) 7915,2023.23 7915.19,2023.04 7990.19,2098.04 7990.19,2258.37 7948.52,2300.04 7948.52,2440.37 7848.52,2540.37 7848.52,2568.04 7848.52,2821.67 7981.86,2955 7981.86,3475.04 7940.19,3516.71 v1(7940.19,3565.37) ; v1@7915,2030.5 ccw(c7915,2048.97) 7928.06,2035.91 ; v1@7915,2034.5 ccw(c7915,2062.62) 7934.89,2042.74 ; v1@7924.5,2025 cw(c7942.25,2025) 7929.7,2037.55 ; v1@7933.47,3558.66 cw(c7917.26,3542.44) 7940.19,3542.44 cw(c7963.13,3542.44) v1@7946.91,3558.66 ; v1@7936.3,3561.49 cw(c7926.91,3552.1) 7940.19,3552.1 cw(c7953.47,3552.1) v1@7944.08,3561.49
  Bottom Layer w4: v2(7403.7,1983.11) 7422.36,2001.76 ; v2@7403.73,1990.11 ccw(c7403.81,2006.74) 7415.57,1994.98 ccw(c7427.33,1983.22) v2@7410.7,1983.14 ; v2@7403.75,1994.11 ccw(c7403.88,2020.24) 7422.35,2001.76 ; v2@7414.7,1983.16 cw(c7440.83,1983.29) 7422.35,2001.76 ; v1@7908.28,2018.28 ccw(c7892.06,2002.06) 7892.06,2025 ccw(c7892.06,2047.93) v1@7908.28,2031.72 ; v1@7911.11,2021.11 ccw(c7901.72,2011.72) 7901.72,2025 ccw(c7901.72,2038.28) v1@7911.11,2028.89 ; v1@7915.19,2023.04 7915,2023.23 v1(7915,2025) 7847.37,2025 7830.75,2008.37 7814.83,2008.37 7790.36,1983.9 7790.36,1972.58 7783.77,1966 7711.23,1966 7702.19,1975.04 7660.52,2016.71 7563.48,2016.71 7555.98,2024.21 7540.32,2024.21 7517.87,2001.76 7422.36,2001.76
HOST_LED1.BLUE: U30.T7 U31.3 | length 5016.8
  Top Layer w4: U31.3@3890.69,3420.99 ccw(c3883.86,3414.16) 3883.86,3423.82 ccw(c3883.86,3433.48) U31.3@3890.69,3426.65 ; U31.3@3920,3423.82 3882.64,3423.82 3864.52,3405.71 3864.52,2945.35 3933.43,2876.45 3933.43,2827.72 4061.15,2700 4165.15,2700 4215.19,2750.04 4256.86,2750.04 4306.86,2700.04 4306.86,1970.45 4348.52,1928.78 v1(4348.52,1900.04) ; v1@4341.81,1906.76 ccw(c4325.59,1922.98) 4348.52,1922.98 ccw(c4371.46,1922.98) v1@4355.24,1906.76 ; v1@4344.64,1903.93 ccw(c4335.25,1913.32) 4348.52,1913.32 ccw(c4361.8,1913.32) v1@4352.41,1903.93
  Top Layer w8: v2@6773.78,2013.48 cw(c6773.78,1991.75) 6789.14,2007.12 cw(c6804.51,2022.48) v2@6782.78,2022.48 ; v2(6773.78,2022.48) U30.T7@6793.46,2002.8 ; U30.T7@6787.62,2002.8 ccw(c6773.52,2002.8) 6783.49,2012.77 ccw(c6793.46,2022.74) U30.T7@6793.46,2008.64
  MidLayer2 w4: v1(5215.19,1858.37) 5215.7,1857.87 5703.97,1857.87 5723.13,1838.71 5895.5,1838.71 5909.17,1825.04 6273.52,1825.04 6315.19,1866.71 6472.31,1866.71 6484.98,1854.04 6755.19,1854.04 6792.86,1891.71 6792.86,2003.4 v2(6773.78,2022.48) ; v2@6773.78,2011.48 cw(c6773.78,1984.92) 6792.56,2003.7 cw(c6811.34,2022.48) v2@6784.78,2022.48 ; v2@6773.78,2015.48 cw(c6773.78,1998.58) 6785.73,2010.53 cw(c6797.68,2022.48) v2@6780.78,2022.48
  Bottom Layer w4: v1(4348.52,1900.04) 4360,1911.52 4360,1960 4372.81,1972.81 4939.44,1972.81 4962.25,1950 5191.92,1950 5215.19,1926.73 v1(5215.19,1858.37) ; v1@5208.47,1865.09 ccw(c5192.26,1881.31) 5215.19,1881.31 ccw(c5238.13,1881.31) v1@5221.91,1865.09 ; v1@5211.3,1862.26 ccw(c5201.91,1871.65) 5215.19,1871.65 ccw(c5228.47,1871.65) v1@5219.08,1862.26
HOST_LED1.GREEN: U30.Y6 U31.5 | length 5166.4
  Top Layer w4: U31.5@3920,3372.64 3967.45,3372.64 3969.86,3375.04 v1(3971.86,3375.04) ; U31.5@3943.12,3372.64 ccw(c3943.12,3403.78) v1@3965.14,3381.76 ; U31.5@3949.31,3369.81 cw(c3956.14,3362.98) 3956.14,3372.64 cw(c3956.14,3382.3) U31.5@3949.31,3375.47 ; 3952.78,3372.64 ccw(c3952.78,3394.12) v1@3967.97,3378.93 ; 3954.72,3372.64 cw(c3954.72,3357.91) v1@3965.14,3368.32
  Top Layer w8: v2@6616.3,2052.85 cw(c6616.3,2031.12) 6631.66,2046.49 cw(c6647.03,2061.85) v2@6625.3,2061.85 ; v2(6616.3,2061.85) U30.Y6@6635.98,2042.17 ; U30.Y6@6630.14,2042.17 ccw(c6616.04,2042.17) 6626.01,2052.14 ccw(c6635.98,2062.11) U30.Y6@6635.98,2048.01
  MidLayer1 w4: v1@3758.47,2880.76 ccw(c3742.26,2896.98) 3765.19,2896.98 ccw(c3788.13,2896.98) v1@3771.91,2880.76 ; v1@3761.3,2877.93 ccw(c3751.91,2887.32) 3765.19,2887.32 ccw(c3778.47,2887.32) v1@3769.08,2877.93 ; v1(3765.19,2874.04) 3765.19,3168.37 v1(3971.86,3375.04) ; v1@3962.36,3375.04 cw(c3939.42,3375.04) 3955.64,3358.82 cw(c3971.86,3342.61) v1@3971.86,3365.54 ; v1@3966.36,3375.04 cw(c3953.08,3375.04) 3962.47,3365.65 cw(c3971.86,3356.26) v1@3971.86,3369.54
  MidLayer2 w4: v1@4225.14,2651.66 ccw(c4208.92,2635.44) 4208.92,2658.37 ccw(c4208.92,2681.31) v1@4225.14,2665.09 ; v1@4227.97,2654.49 ccw(c4218.58,2645.1) 4218.58,2658.37 ccw(c4218.58,2671.65) v1@4227.97,2662.26 ; v1(4231.86,2658.37) 4021.86,2658.37 4006.86,2643.37 4006.86,2491.71 4031.86,2466.71 4431.86,2466.71 4532.71,2567.56 4617.56,2567.56 4691.71,2641.71 4896.52,2641.71 4929.86,2608.37 5116.19,2608.37 5124.52,2616.71 5200,2616.71 5215,2601.71 5215,2575.32 5248.94,2541.37 5644.48,2541.37 5690.86,2495 5690.86,2198.08 5718.57,2170.37 6414.5,2170.37 6493.17,2091.71 6581.86,2091.71 6611.72,2061.85 v2(6616.3,2061.85)
  Bottom Layer w4: v1@3765.19,2864.54 cw(c3765.19,2841.61) 3781.41,2857.82 cw(c3797.63,2874.04) v1@3774.69,2874.04 ; v1@3765.19,2868.54 cw(c3765.19,2855.26) 3774.58,2864.65 cw(c3783.97,2874.04) v1@3770.69,2874.04 ; v1(3765.19,2874.04) 3872.52,2766.71 4162.21,2766.71 4231.86,2697.06 v1(4231.86,2658.37) ; v1@4225.14,2665.09 ccw(c4208.92,2681.31) 4231.86,2681.31 ccw(c4254.79,2681.31) v1@4238.57,2665.09 ; v1@4227.97,2662.26 ccw(c4218.58,2671.65) 4231.86,2671.65 ccw(c4245.14,2671.65) v1@4235.75,2662.26
HOST_LED1.RED: U30.U6 U31.1 | length 4851.1
  Top Layer w4: U31.1@3917.17,3477.83 ccw(c3910.34,3484.66) 3920,3484.66 ccw(c3929.66,3484.66) U31.1@3922.83,3477.83 ; U31.1@3920,3475 3920,3511.9 3906.86,3525.04 3885,3525.04 3860,3525 3845,3510 3845,3430 3856.52,3418.48 3856.52,2942.04 3925.43,2873.13 3925.43,2824.41 4280,2469.84 v4(4280,2345) ; v4@4273.06,2351.94 ccw(c4256.31,2368.69) 4280,2368.69 ccw(c4303.69,2368.69) v4@4286.94,2351.94 ; v4@4275.89,2349.11 ccw(c4265.97,2359.03) 4280,2359.03 ccw(c4294.03,2359.03) v4@4284.11,2349.11
  Top Layer w8: v2@6734.41,2052.85 cw(c6734.41,2031.12) 6749.77,2046.49 cw(c6765.14,2061.85) v2@6743.41,2061.85 ; v2(6734.41,2061.85) U30.U6@6754.09,2042.17 ; U30.U6@6748.25,2042.17 ccw(c6734.15,2042.17) 6744.12,2052.14 ccw(c6754.09,2062.11) U30.U6@6754.09,2048.01
  MidLayer2 w4: v4(4280,2345) 4316.63,2345 4330,2358.37 4881.86,2358.37 4891.02,2349.21 4916.11,2349.21 4926.36,2359.46 4926.36,2488.62 4925,2489.98 4925,2519.75 4955.25,2550 5080.23,2550 5088.86,2541.37 5215,2541.37 5239.67,2516.71 5571.54,2516.71 5665.19,2423.06 5665.19,2189.81 5708.63,2146.37 5963.52,2146.37 6012.57,2097.32 6012.5,2097.25 6012.5,2077.75 6027.75,2062.5 6043.65,2062.5 6083.15,2102 6384.69,2102 6387.69,2105 6400,2105 6410.64,2094.36 6410.64,2081.07 6450,2041.71 6560.19,2041.71 6598.52,2003.37 6665.19,2003.37 6675.19,2013.37 6675.19,2033.37 6683.52,2041.71 6714.27,2041.71 v2(6734.41,2061.85) ; v4@4284.11,2340.89 cw(c4294.03,2330.97) 4294.03,2345 cw(c4294.03,2359.03) v4@4284.11,2349.11 ; v4@4286.94,2338.06 cw(c4303.69,2321.31) 4303.69,2345 cw(c4303.69,2368.69) v4@4286.94,2351.94 ; 6722.46,2049.9 ccw(c6710.51,2061.85) v2@6727.41,2061.85 ; 6722.46,2049.9 cw(c6734.41,2037.95) v2@6734.41,2054.85 ; v2@6723.41,2061.85 cw(c6696.85,2061.85) 6715.63,2043.07 cw(c6734.41,2024.3) v2@6734.41,2050.85
HOST_LED2.BLUE: U30.W4 U31.11 | length 4386.4
  Top Layer w4: U31.11@4138.5,3398.23 4171.77,3398.23 ; v1@4141.81,2740.09 ccw(c4125.59,2756.31) 4148.52,2756.31 ccw(c4171.46,2756.31) v1@4155.24,2740.09 ; v1@4144.64,2737.26 ccw(c4135.25,2746.65) 4148.52,2746.65 ccw(c4161.8,2746.65) v1@4152.41,2737.26 ; v1(4148.52,2733.37) 4148.52,3033.33 4131.86,3050 4131.86,3080 4181.86,3130 4181.86,3388.14 4171.77,3398.23 ; U31.11@4167.56,3395.16 cw(c4171.18,3390.85) 4175.17,3394.83 ; U31.11@4168.48,3396.29 cw(c4171.77,3394.47) 4171.77,3398.23 ; U31.11@4168.48,3400.17 ccw(c4171.77,3401.99) 4171.77,3398.23 ; 4172.08,3397.92 ccw(c4168.36,3394.2) 4164.98,3398.23 cw(c4164.98,3381.84) 4176.57,3393.43
  Top Layer w8: v2@6655.67,2131.59 cw(c6655.67,2109.86) 6671.03,2125.23 cw(c6686.4,2140.59) v2@6664.67,2140.59 ; v2(6655.67,2140.59) U30.W4@6675.35,2120.91 ; U30.W4@6669.51,2120.91 ccw(c6655.41,2120.91) 6665.38,2130.88 ccw(c6675.35,2140.85) U30.W4@6675.35,2126.75
  MidLayer1 w4: v1(5565.19,2583.37) 5598.52,2583.37 5623.52,2558.37 5623.52,2475.04 5665.19,2433.37 5665.19,2169.08 5684.23,2150.04 6004.96,2150.04 6030,2125 v1(6030,2085) ; v1@5569.08,2579.49 cw(c5578.47,2570.1) 5578.47,2583.37 cw(c5578.47,2596.65) v1@5569.08,2587.26 ; v1@5571.91,2576.66 cw(c5588.13,2560.44) 5588.13,2583.37 cw(c5588.13,2606.31) v1@5571.91,2590.09 ; v1@6023.28,2091.72 ccw(c6007.06,2107.93) 6030,2107.93 ccw(c6052.93,2107.93) v1@6036.72,2091.72 ; v1@6026.11,2088.89 ccw(c6016.72,2098.28) 6030,2098.28 ccw(c6043.28,2098.28) v1@6033.89,2088.89
  MidLayer2 w4: v1(4148.52,2733.37) 4191.67,2733.37 4225,2700.04 4845.52,2700.04 4920.52,2775.04 5106.19,2775.04 5181.86,2699.37 5231.86,2699.37 5240.86,2708.37 5490.19,2708.37 5565.19,2633.37 v1(5565.19,2583.37) ; v1@4152.41,2729.49 cw(c4161.8,2720.1) 4161.8,2733.37 cw(c4161.8,2746.65) v1@4152.41,2737.26 ; v1@4155.24,2726.66 cw(c4171.46,2710.44) 4171.46,2733.37 cw(c4171.46,2756.31) v1@4155.24,2740.09 ; v1@5558.47,2590.09 ccw(c5542.26,2606.31) 5565.19,2606.31 ccw(c5588.13,2606.31) v1@5571.91,2590.09 ; v1@5561.3,2587.26 ccw(c5551.91,2596.65) 5565.19,2596.65 ccw(c5578.47,2596.65) v1@5569.08,2587.26 ; v1(6030,2085) 6055,2110 6380,2110 6385,2115 6412.23,2115 v1(6427.19,2100.04) ; v1@6030,2090.5 ccw(c6030,2103.78) 6039.39,2094.39 ccw(c6048.78,2085) v1@6035.5,2085 ; v1@6030,2094.5 ccw(c6030,2117.43) 6046.22,2101.22 ccw(c6062.43,2085) v1@6039.5,2085
  Bottom Layer w4: v1(6427.19,2100.04) 6448.52,2121.37 6636.52,2121.37 6640.19,2125.04 6640.19,2125.11 v2(6655.67,2140.59) ; v1@6427.19,2105.54 ccw(c6427.19,2118.82) 6436.58,2109.43 ccw(c6445.97,2100.04) v1@6432.69,2100.04 ; v1@6427.19,2109.54 ccw(c6427.19,2132.48) 6443.41,2116.26 ccw(c6459.63,2100.04) v1@6436.69,2100.04
HOST_LED2.GREEN: U30.Y4 U31.13 | length 4242.6
  Top Layer w4: v1@4089.81,2808.76 ccw(c4073.59,2824.98) 4096.52,2824.98 ccw(c4119.46,2824.98) v1@4103.24,2808.76 ; v1@4092.64,2805.93 ccw(c4083.25,2815.32) 4096.52,2815.32 ccw(c4109.8,2815.32) v1@4100.41,2805.93 ; v1(4096.52,2802.04) 4096.52,3273.48 4057.19,3312.81 4057.19,3338 3994.36,3400.83 3994.36,3423.96 4012.94,3442.54 4024.73,3442.54 4040.23,3458.04 4089.89,3458.04 4098.52,3449.41 U31.13@4138.5,3449.41 ; U31.13@4109.2,3446.58 ccw(c4102.37,3439.75) 4102.37,3449.41 ccw(c4102.37,3459.07) U31.13@4109.2,3452.24
  Top Layer w8: v2@6616.3,2131.59 cw(c6616.3,2109.86) 6631.66,2125.23 cw(c6647.03,2140.59) v2@6625.3,2140.59 ; v2(6616.3,2140.59) U30.Y4@6635.98,2120.91 ; U30.Y4@6630.14,2120.91 ccw(c6616.04,2120.91) 6626.01,2130.88 ccw(c6635.98,2140.85) U30.Y4@6635.98,2126.75
  MidLayer2 w4: v1(4473.52,2725.04) 4618.86,2725.04 4632.76,2738.95 4703.19,2809.37 5049.52,2809.37 5081.86,2841.71 5210.52,2841.71 5252.19,2800.04 5441.92,2800.04 5458.59,2816.71 5487.86,2816.71 5562.86,2741.71 5723.52,2741.71 5798.52,2666.71 5798.52,2518.54 5867.02,2450.04 6015.19,2450.04 6156.86,2308.37 6323.52,2308.37 6348.52,2283.37 6348.52,2233.37 6379.52,2202.37 6427.76,2202.37 6489.54,2140.59 v2(6616.3,2140.59) v2@6616.3,2141.71 ; v1@4477.41,2721.15 cw(c4486.8,2711.76) 4486.8,2725.04 cw(c4486.8,2738.32) v1@4477.41,2728.93 ; v1@4480.24,2718.32 cw(c4496.46,2702.11) 4496.46,2725.04 cw(c4496.46,2747.98) v1@4480.24,2731.76 ; v2@6608.52,2132.81 ccw(c6589.74,2114.03) 6589.74,2140.59 ccw(c6589.74,2167.15) v2@6608.52,2148.37 ; v2@6611.35,2135.64 ccw(c6599.4,2123.69) 6599.4,2140.59 ccw(c6599.4,2157.49) v2@6611.35,2145.54
  Bottom Layer w4: v1@4096.52,2792.54 cw(c4096.52,2769.61) 4112.74,2785.82 cw(c4128.96,2802.04) v1@4106.02,2802.04 ; v1@4096.52,2796.54 cw(c4096.52,2783.26) 4105.91,2792.65 cw(c4115.3,2802.04) v1@4102.02,2802.04 ; v1(4096.52,2802.04) 4115.19,2783.37 4168.17,2783.37 4201.5,2750.04 4281.86,2750.04 4306.86,2725.04 v1(4473.52,2725.04) ; v1@4466.81,2718.32 ccw(c4450.59,2702.11) 4450.59,2725.04 ccw(c4450.59,2747.98) v1@4466.81,2731.76 ; v1@4469.64,2721.15 ccw(c4460.25,2711.76) 4460.25,2725.04 ccw(c4460.25,2738.32) v1@4469.64,2728.93
HOST_LED2.RED: U30.Y5 U31.9 | length 3845.7
  Top Layer w4: v1(4090.19,3333.37) 4103.86,3347.05 ; U31.9@4108.86,3344.6 ccw(c4103.86,3340.73) 4103.86,3347.05 ; U31.9@4108.86,3349.5 cw(c4103.86,3353.37) 4103.86,3347.05 ; U31.9@4140.19,3347.05 U31.9@4138.5,3347.05 4103.86,3347.05
  Top Layer w8: v2@6616.3,2092.22 cw(c6616.3,2070.49) 6631.66,2085.86 cw(c6647.03,2101.22) v2@6625.3,2101.22 ; v2(6616.3,2101.22) U30.Y5@6635.98,2081.54 ; U30.Y5@6630.14,2081.54 ccw(c6616.04,2081.54) 6626.01,2091.51 ccw(c6635.98,2101.48) U30.Y5@6635.98,2087.38
  MidLayer1 w4: v1(5415.19,2891.71) 5405.52,2882.04 5405.52,2801.37 v1(5431.86,2775.04) ; v1@5422.36,2775.04 ccw(c5399.42,2775.04) 5415.64,2791.26 ccw(c5431.86,2807.48) v1@5431.86,2784.54 ; v1@5426.36,2775.04 ccw(c5413.08,2775.04) 5422.47,2784.43 ccw(c5431.86,2793.82) v1@5431.86,2780.54
  MidLayer2 w4: v1(5431.86,2775.04) 5465.19,2808.37 5484.88,2808.37 5559.88,2733.37 5720.54,2733.37 5790.52,2663.39 5790.52,2515.22 5915.19,2390.56 5915.19,2303.04 6031.86,2186.37 6421.13,2186.37 6499.13,2108.37 6616.3,2108.37 v2(6616.3,2101.22) ; v1@5431.86,2780.54 ccw(c5431.86,2793.82) 5441.25,2784.43 ccw(c5450.64,2775.04) v1@5437.36,2775.04 ; v1@5431.86,2784.54 ccw(c5431.86,2807.48) 5448.07,2791.26 ccw(c5464.29,2775.04) v1@5441.36,2775.04
  Bottom Layer w4: v1(4090.19,3333.37) 4076.19,3319.37 4076.19,3036.67 4121.82,2991.04 4418.48,2991.04 4484.48,2925.04 4798.52,2925.04 4865.19,2858.37 5103.82,2858.37 5121.15,2841.04 5184.88,2841.04 5245.21,2901.37 5314.46,2901.37 5322.29,2893.54 5343.42,2893.54 5352.08,2902.2 5374.34,2902.2 5384.84,2891.71 v1(5415.19,2891.71) ; v1@5408.47,2884.99 ccw(c5392.26,2868.77) 5392.26,2891.71 ccw(c5392.26,2914.64) v1@5408.47,2898.43 ; v1@5411.3,2887.82 ccw(c5401.91,2878.43) 5401.91,2891.71 ccw(c5401.91,2904.99) v1@5411.3,2895.6
HOST_M0: R158.1 U30.V4 | length 1787.6
  Top Layer w8: v2@6695.04,2131.59 cw(c6695.04,2109.86) 6710.4,2125.23 cw(c6725.77,2140.59) v2@6704.04,2140.59 ; v2(6695.04,2140.59) U30.V4@6714.72,2120.91 ; U30.V4@6708.88,2120.91 ccw(c6694.78,2120.91) 6704.75,2130.88 ccw(c6714.72,2140.85) U30.V4@6714.72,2126.75
  MidLayer1 w4: v1(5850,2080) 5881.86,2048.14 5881.86,1791.71 ; v1(5857.86,1775.04) 5865.19,1775.04 5881.86,1791.71 ; v1@5858.09,1776.52 ccw(c5860.41,1791) 5870.78,1780.63 ; v1@5858.73,1780.47 ccw(c5861.95,1800.54) 5876.32,1786.17 ; v1@5859.36,1784.42 ccw(c5863.48,1810.09) 5881.86,1791.71 ; v1@5867.36,1775.04 cw(c5872.59,1775.04) 5868.89,1778.74 ; 5859.39,2070.61 cw(c5868.78,2080) 5855.5,2080 ccw(c5868.78,2080) 5859.39,2070.61 ; 5859.39,2070.61 ccw(c5850,2061.22) 5850,2074.5 cw(c5850,2061.22) 5859.39,2070.61 ; 5866.22,2063.78 cw(c5882.43,2080) 5859.5,2080 ccw(c5882.43,2080) 5866.22,2063.78 ; 5866.22,2063.78 ccw(c5850,2047.56) 5850,2070.5 cw(c5850,2047.56) 5866.22,2063.78
  Bottom Layer w4: R158.1@5833.29,1737.08 ccw(c5817.38,1752.99) 5839.88,1752.99 ccw(c5862.37,1752.99) R158.1@5846.46,1737.08 ; R158.1@5836.11,1734.25 ccw(c5827.03,1743.33) 5839.88,1743.33 ccw(c5852.71,1743.33) R158.1@5843.64,1734.25 ; R158.1@5839.87,1730 5839.88,1764.73 5850.19,1775.04 v1(5857.86,1775.04) ; 5840.86,1765.71 cw(c5852.05,1754.53) v1@5856.36,1769.75 ; 5845.68,1770.53 cw(c5854.18,1762.04) v1@5857.45,1773.6 ; v1@5850,2070.5 cw(c5850,2047.32) 5866.39,2063.71 ; v1@5850,2074.5 cw(c5850,2060.98) 5859.56,2070.54 ; v1(5850,2080) 5850.05,2080.05 5867.1,2063 5999.56,2063 6040.38,2022.19 6354,2022.19 6356.19,2024.37 6413.86,2082.04 6626.86,2082.04 6636.52,2091.71 6636.52,2109.37 6647.52,2120.37 6674.82,2120.37 v2(6695.04,2140.59) ; v1@5855.5,2080 ccw(c5868.53,2080) 5859.32,2070.78 ; v1@5859.5,2080 ccw(c5882.19,2080) 5866.15,2063.96 ; v2@6684.04,2140.59 cw(c6657.48,2140.59) 6676.26,2121.81 cw(c6695.04,2103.04) v2@6695.04,2129.59 ; v2@6688.04,2140.59 cw(c6671.14,2140.59) 6683.09,2128.64 cw(c6695.04,2116.69) v2@6695.04,2133.59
